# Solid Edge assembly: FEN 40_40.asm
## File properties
Title: Zylinder
Author: bmolnar
Template: iso assembly.asm
Last saved by: bmolnar
Revision: 15
Application: Solid Edge
Username: bmolnar
Dokumentum tartalom típus: 1
Document Number: FEN 40/40
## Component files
Kolbenstange.par
Profilrohr.par
Kit_1.par
Kit_2.par
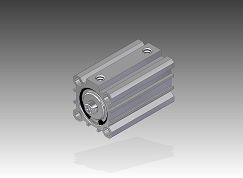
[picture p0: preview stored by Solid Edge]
